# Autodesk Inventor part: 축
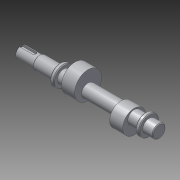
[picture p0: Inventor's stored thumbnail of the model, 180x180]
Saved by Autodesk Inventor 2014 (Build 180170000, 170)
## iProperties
Created: 2014-12
Part Number: 축
Material: 알루미늄 6061
Document SubType Name: Modeling
Designer: Owner
Density: 2.71 g/cm^3
Appearance: 알루미늄 - 평지
Mass: 170.285 g
Surface Area: 153.076 cm^2
Volume: 62.8357 cm^3
Author: Owner
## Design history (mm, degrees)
sketch "스케치1"
  geometry: L1 (-90, 0)-(90, 0); L2 (-90, 0)-(-90, 7.5); L3 (-90, 7.5)-(-66, 7.5); L4 (-66, 7.5)-(-66, 8.5); L5 (-66, 8.5)-(-39, 8.5); L6 (-39, 8.5)-(-39, 13); L7 (-39, 13)-(-34, 13); L8 (-34, 13)-(-34, 8.5); L9 (-34, 8.5)-(72, 8.5); L10 (72, 8.5)-(72, 13); L11 (72, 13)-(77, 13); L12 (77, 13)-(77, 8.5); L13 (77, 8.5)-(90, 8.5); L14 (90, 8.5)-(90, 0); 2 further points
  constraints: 28 end point, 11 parallel, 2 horizontal alignment, 2 perpendicular, 1 coincident, 1 horizontal, 1 midpoint
  dimensions: "d12" = 180 distance of L1.start L1.end; "d13" = 15 diameter of L3 L1; "d14" = 17 diameter of L5 L1; "d15" = 24 distance of L2.end L3.end; "d16" = 26 diameter of L7 L1; "d17" = 5 distance of L6.end L7.end; "d18" = 27 distance of L4.end L5.end; "d19" = 13 distance of L12.end L13.end; "d20" = 5 distance of L10.end L11.end; "d21" = 26 diameter of L11 L1
revolve "회전1" sketch "스케치1" stored, may be unused: angle "d22" = 90 deg
node "작업 평면1"
sketch "스케치2"
  geometry: C1 r 17.5 at (-6, 0); 1 further point
  constraints: 1 centre point, 1 horizontal alignment
  dimensions: "d24" = 35 diameter of C1; "d25" = 6 distance of point (0, 0) C1.centre
extrude "돌출1" join sketch "스케치2" distance "d26" = 17; taper "d27" = 0 deg
node "작업 평면2"
sketch "스케치3"
  geometry: C1 r 15 at (-5, 0); 1 further point
  constraints: 1 centre point, 1 horizontal alignment
  dimensions: "d29" = 30 diameter of C1; "d30" = 5 distance of point (0, 0) C1.centre
extrude "돌출2" join sketch "스케치3" distance "d31" = 17; taper "d32" = 0 deg
node "작업 평면3"
sketch "스케치4"
  geometry: L1 (-12, 2.5)-(5.5, 2.5); L2 (-12, -2.5)-(5.5, -2.5); L3 (-12, -7.5)-(-12, 7.5) reference; L4 (-12, 2.5)-(-12, -2.5); A1 r 2.5 centre (5.5, 0) between (5.5, -2.5) and (5.5, 2.5); 1 further point
  constraints: 6 end point, 2 parallel, 2 point on circle, 2 tangent, 1 centre point, 1 collinear, 1 horizontal, 1 horizontal alignment, 1 perpendicular, 1 point on line
  dimensions: "d38" = 5 distance between parallel lines of L2 L1; "d39" = 20 dimension on A1 L3
extrude "돌출3" cut sketch "스케치4" distance "d40" = 3; taper "d41" = 0 deg
chamfer "모따기1" distance "d42" = 1; stored, may be unused: second distance "d43" = 2, angle "d44" = 45 deg
node "솔리드1"
other parameters: "d23" = 14.5, "d28" = 14.5
